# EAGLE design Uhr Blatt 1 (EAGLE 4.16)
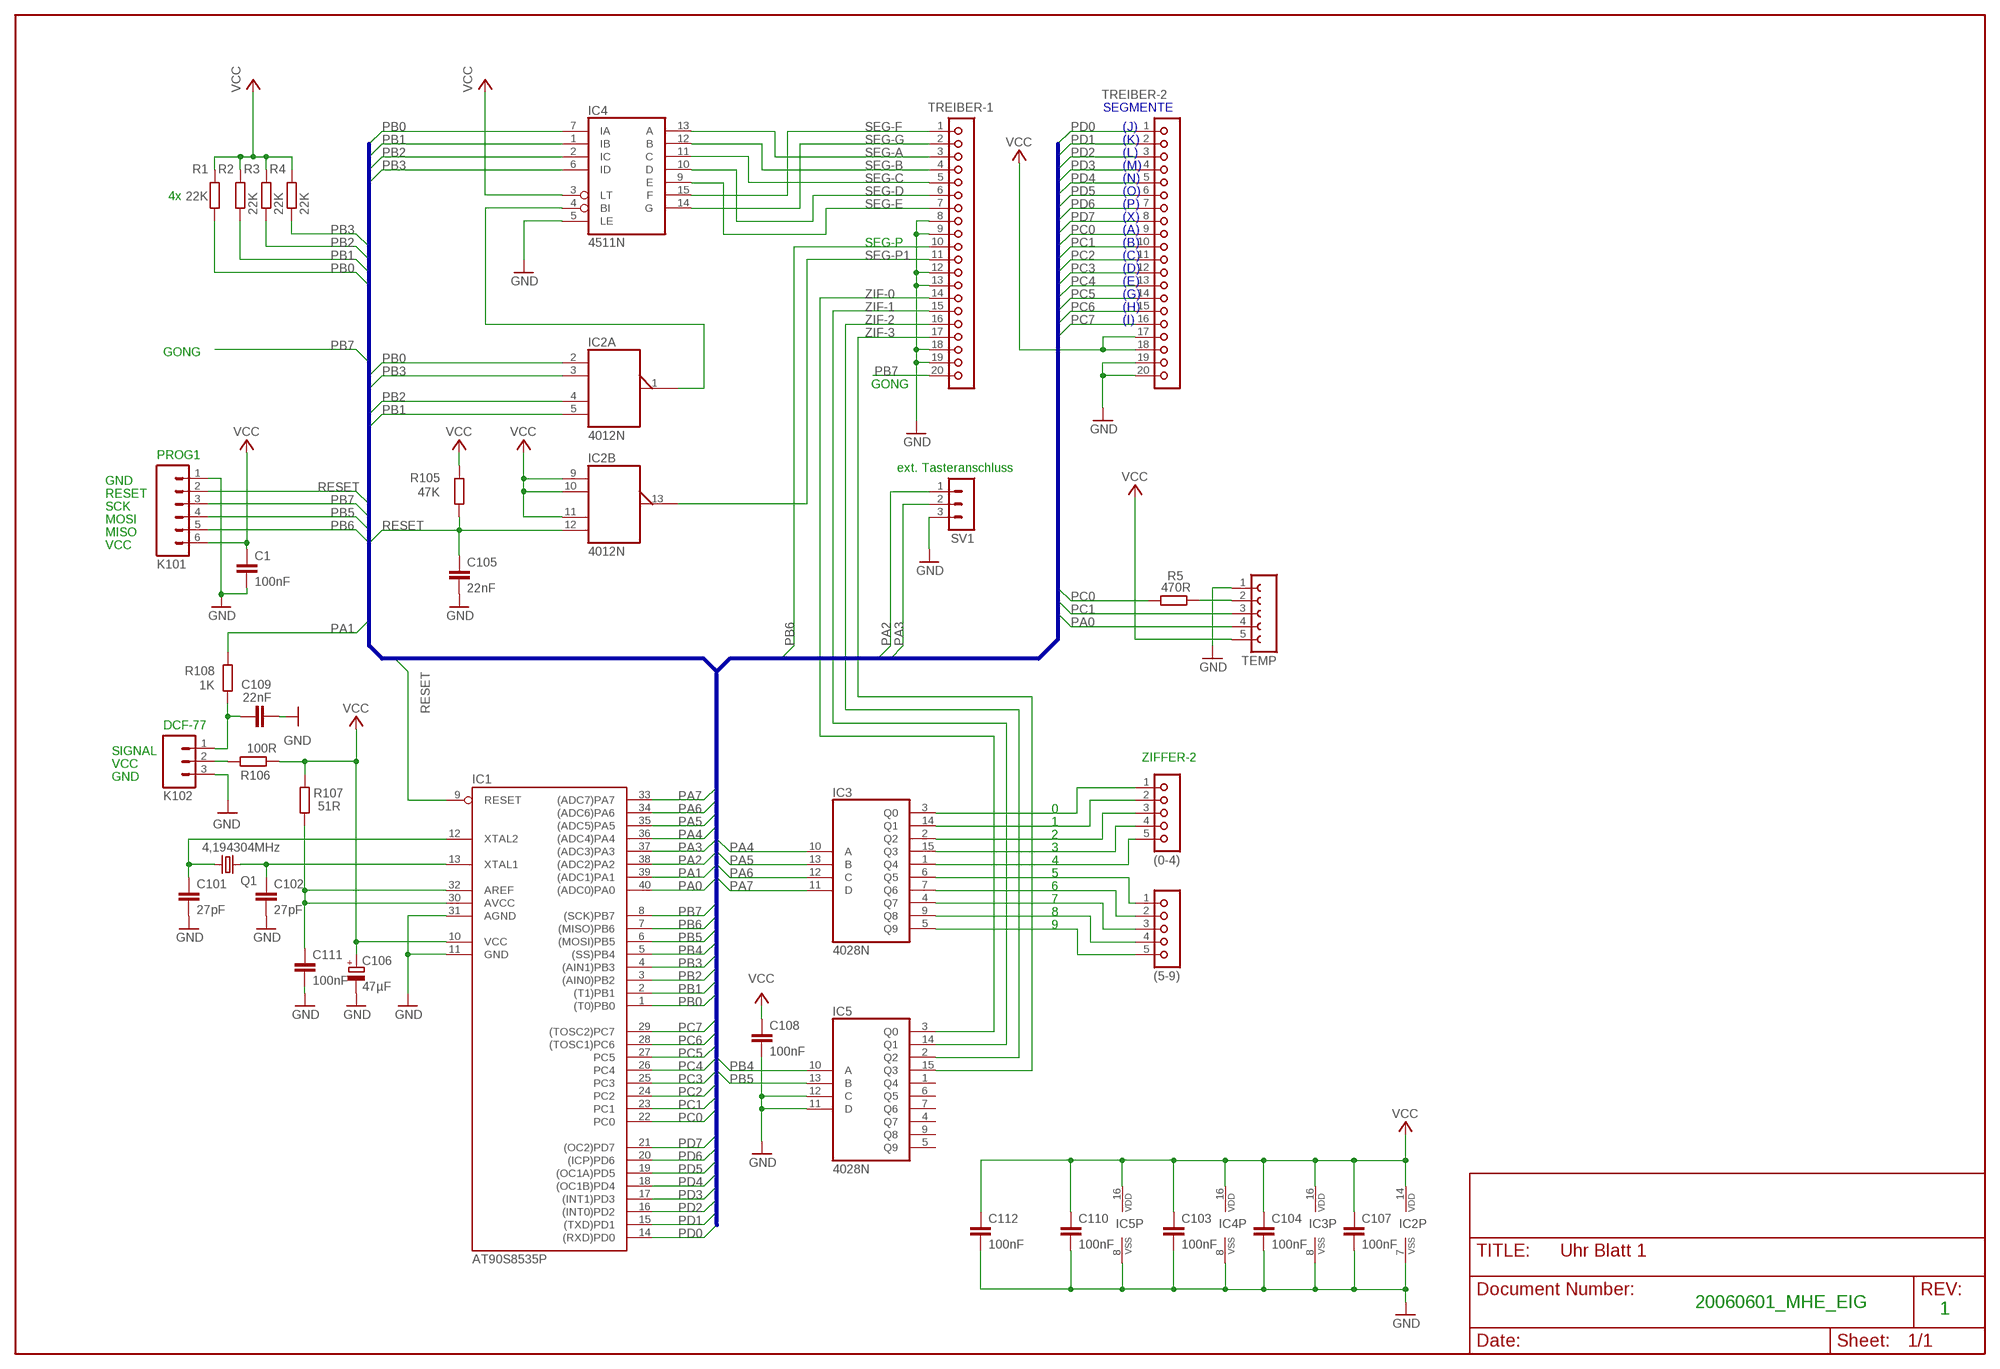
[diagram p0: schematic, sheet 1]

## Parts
(0-4)  JU05  [JU05]
(5-9)  JU05  [JU05]
C1  100nF  C-EU050-024X044  [C050-024X044]
C101  27pF  C-EU025-024X044  [C025-024X044]
C102  27pF  C-EU025-024X044  [C025-024X044]
C103  100nF  C-EU050-024X044  [C050-024X044]
C104  100nF  C-EU050-024X044  [C050-024X044]
C105  22nF  C-EU050-024X044  [C050-024X044]
C106  47µF  CPOL-EUE2,5-6E  [E2,5-6E]
C107  100nF  C-EU050-024X044  [C050-024X044]
C108  100nF  C-EU050-024X044  [C050-024X044]
C109  22nF  C-EU050-024X044  [C050-024X044]
C110  100nF  C-EU050-024X044  [C050-024X044]
C111  100nF  C-EU050-024X044  [C050-024X044]
C112  100nF  C-EU050-024X044  [C050-024X044]
IC1  AT90S8535P  [DIL40]
IC2  4012N  [DIL14]
IC3  4028N  [DIL16]
IC4  4511N  [DIL16]
IC5  4028N  [DIL16]
K101  M06  [06P]
K102  M03  [03P]
Q1  4,194304MHz  CRYTALHC49U-V  [HC49U-V]
R1  22K  R-EU_0207/10  [0207/10]
R2  22K  R-EU_0207/10  [0207/10]
R3  22K  R-EU_0207/10  [0207/10]
R4  22K  R-EU_0207/10  [0207/10]
R5  470R  R-EU_0207/10  [0207/10]
R105  47K  R-EU_0207/10  [0207/10]
R106  100R  R-EU_0207/10  [0207/10]
R107  51R  R-EU_0207/10  [0207/10]
R108  1K  R-EU_0207/10  [0207/10]
SV1  MA03-1  [MA03-1]
TEMP  FE05-1  [FE05-1]
TREIBER-1  JU20  [JU20]
TREIBER-2  JU20  [JU20]

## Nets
AVCC: C111.1 IC1.30(AVCC) IC1.32(AREF) R107.1
DCF77: C109.1 K102.1 R108.1
GND: C1.2 C101.2 C102.2 C103.2 C104.2 C105.2 C106.- C107.2 C108.2 C109.2 C110.2 C111.2 C112.2 IC1.11(GND) IC1.31(AGND) IC2.7(P:VSS) IC3.8(VSS) IC4.5(LE) IC4.8(VSS) IC5.8(VSS) IC5.11(D) IC5.12(C) K101.1 K102.3 SV1.3 TEMP.1 TREIBER-1.8 TREIBER-1.9 TREIBER-1.12 TREIBER-1.13 TREIBER-1.18 TREIBER-1.19 TREIBER-2.19 TREIBER-2.20
N$1: IC2.1 IC4.4(BI)
N$2: C101.1 IC1.12(XTAL2) Q1.1
N$3: C102.1 IC1.13(XTAL1) Q1.2
N$5: K102.2 R106.1
N$6: (0-4).1 IC3.3(Q0)
N$7: (0-4).2 IC3.14(Q1)
N$8: (0-4).3 IC3.2(Q2)
N$9: (0-4).4 IC3.15(Q3)
N$10: (0-4).5 IC3.1(Q4)
N$11: (5-9).1 IC3.6(Q5)
N$12: (5-9).2 IC3.7(Q6)
N$13: (5-9).3 IC3.4(Q7)
N$14: (5-9).4 IC3.9(Q8)
N$15: (5-9).5 IC3.5(Q9)
N$16: R5.2 TEMP.2
PA0: IC1.40((ADC0)PA0) TEMP.4
PA1: IC1.39((ADC1)PA1) R108.2
PA2: IC1.38((ADC2)PA2) SV1.1
PA3: IC1.37((ADC3)PA3) SV1.2
PA4: IC1.36((ADC4)PA4) IC3.10(A)
PA5: IC1.35((ADC5)PA5) IC3.13(B)
PA6: IC1.34((ADC6)PA6) IC3.12(C)
PA7: IC1.33((ADC7)PA7) IC3.11(D)
PB0: IC1.1((T0)PB0) IC2.2(A:I0) IC4.7(IA) R1.1
PB1: IC1.2((T1)PB1) IC2.5(A:I3) IC4.1(IB) R2.1
PB2: IC1.3((AIN0)PB2) IC2.4(A:I2) IC4.2(IC) R3.1
PB3: IC1.4((AIN1)PB3) IC2.3(A:I1) IC4.6(ID) R4.1
PB4: IC1.5((SS)PB4) IC5.10(A)
PB5: IC1.6((MOSI)PB5) IC5.13(B) K101.4
PB6: IC1.7((MISO)PB6) K101.5 TREIBER-1.10
PB7: IC1.8((SCK)PB7) K101.3 TREIBER-1.20
PC0: IC1.22(PC0) R5.1 TREIBER-2.9
PC1: IC1.23(PC1) TEMP.3 TREIBER-2.10
PC2: IC1.24(PC2) TREIBER-2.11
PC3: IC1.25(PC3) TREIBER-2.12
PC4: IC1.26(PC4) TREIBER-2.13
PC5: IC1.27(PC5) TREIBER-2.14
PC6: IC1.28((TOSC1)PC6) TREIBER-2.15
PC7: IC1.29((TOSC2)PC7) TREIBER-2.16
PD0: IC1.14((RXD)PD0) TREIBER-2.1
PD1: IC1.15((TXD)PD1) TREIBER-2.2
PD2: IC1.16((INT0)PD2) TREIBER-2.3
PD3: IC1.17((INT1)PD3) TREIBER-2.4
PD4: IC1.18((OC1B)PD4) TREIBER-2.5
PD5: IC1.19((OC1A)PD5) TREIBER-2.6
PD6: IC1.20((ICP)PD6) TREIBER-2.7
PD7: IC1.21((OC2)PD7) TREIBER-2.8
RESET: C105.1 IC1.9(RESET) IC2.12(B:I3) K101.2 R105.1
SEG-A: IC4.13(A) TREIBER-1.3
SEG-B: IC4.12(B) TREIBER-1.4
SEG-C: IC4.11(C) TREIBER-1.5
SEG-D: IC4.10(D) TREIBER-1.6
SEG-E: IC4.9(E) TREIBER-1.7
SEG-F: IC4.15(F) TREIBER-1.1
SEG-G: IC4.14(G) TREIBER-1.2
SEG-P1: IC2.13 TREIBER-1.11
VCC: C1.1 C103.1 C104.1 C106.+ C107.1 C108.1 C110.1 C112.1 IC1.10(VCC) IC2.9(B:I0) IC2.10(B:I1) IC2.11(B:I2) IC2.14(P:VDD) IC3.16(VDD) IC4.3(LT) IC4.16(VDD) IC5.16(VDD) K101.6 R1.2 R2.2 R3.2 R4.2 R105.2 R106.2 R107.2 TEMP.5 TREIBER-2.17 TREIBER-2.18
ZIF-0: IC5.3(Q0) TREIBER-1.14
ZIF-1: IC5.14(Q1) TREIBER-1.15
ZIF-2: IC5.2(Q2) TREIBER-1.16
ZIF-3: IC5.15(Q3) TREIBER-1.17
Unconnected: IC5.1(Q4) IC5.4(Q7) IC5.5(Q9) IC5.6(Q5) IC5.7(Q6) IC5.9(Q8)

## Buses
B$1

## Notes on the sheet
- SEGMENTE
- (J)
- (K)
- (L)
- (M)
- (N)
- (O)
- 4x
- (P)
- (X)
- (A)
- SEG-P | (B)
- (C)
- (D)
- (E)
- (G)
- (H)
- (I)
- GONG
- GONG
- PROG1
- ext. Tasteranschluss
- GND
- RESET
- SCK
- MOSI
- MISO
- VCC
- DCF-77
- SIGNAL
- ZIFFER-2
- VCC
- GND
- 0
- 1
- 2
- 3
- 4
- 5
- 6
- 7
- 8
- 9
- 20060601_MHE_EIG
- 1

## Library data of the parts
(0-4) (5-9) = con-lsta:JU05: PIN HEADER
C1 C101-C105 C107-C112 = rcl:C-EU: CAPACITOR, European symbol
C106 = rcl:CPOL-EU: POLARIZED CAPACITOR, European symbol
IC1 = atmel:AT90*8535P: MICROCONTROLLER 8 Kbytes FLASH 512 bytes SRAM 512 bytes EEPROM UART 8-channel 10 bit ADC
IC2 = 40xx:4012N
IC3 IC5 = 40xx:4028: BCD to decimal DECODER
IC4 = 45xx:4511: BCD to 7-segment LATCH/DECODER/DRIVER
K101 = con-amp-quick:M06: AMP QUICK CONNECTOR
K102 = con-amp-quick:M03: AMP QUICK CONNECTOR
Q1 = crystal:CRYTAL: CRYSTAL
R1-R5 R105-R108 = rcl:R-EU_: RESISTOR, European symbol
SV1 = con-lstb:MA03-1: PIN HEADER
TEMP = con-lsta:FE05-1: FEMALE HEADER
TREIBER-1 TREIBER-2 = con-lsta:JU20: PIN HEADER

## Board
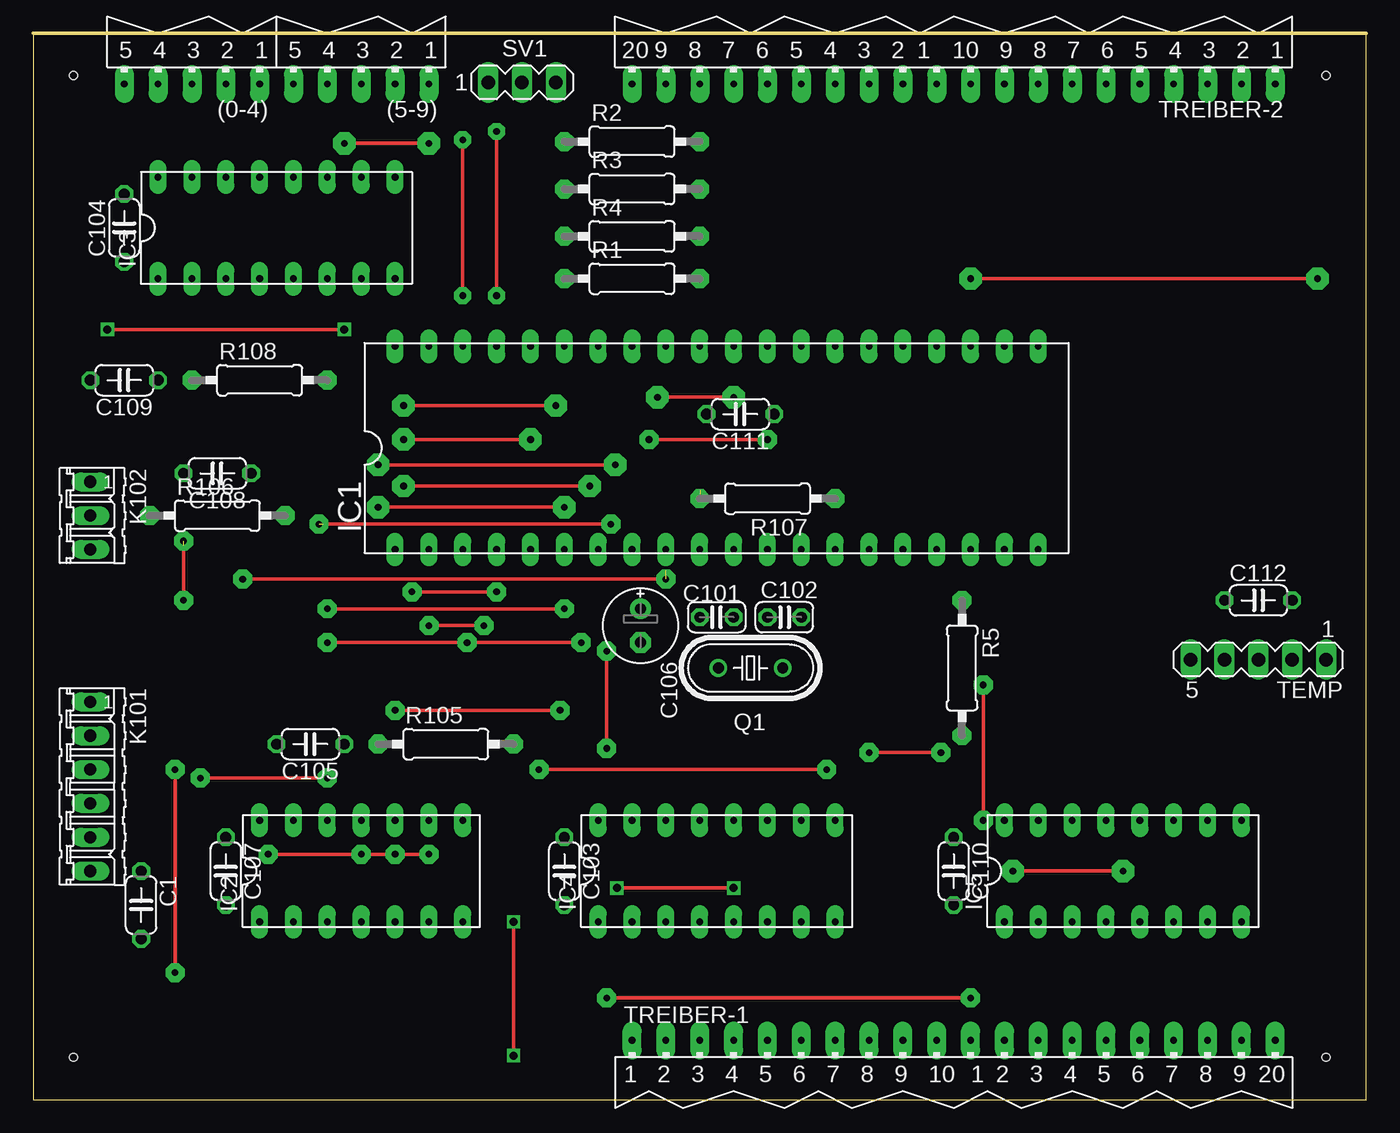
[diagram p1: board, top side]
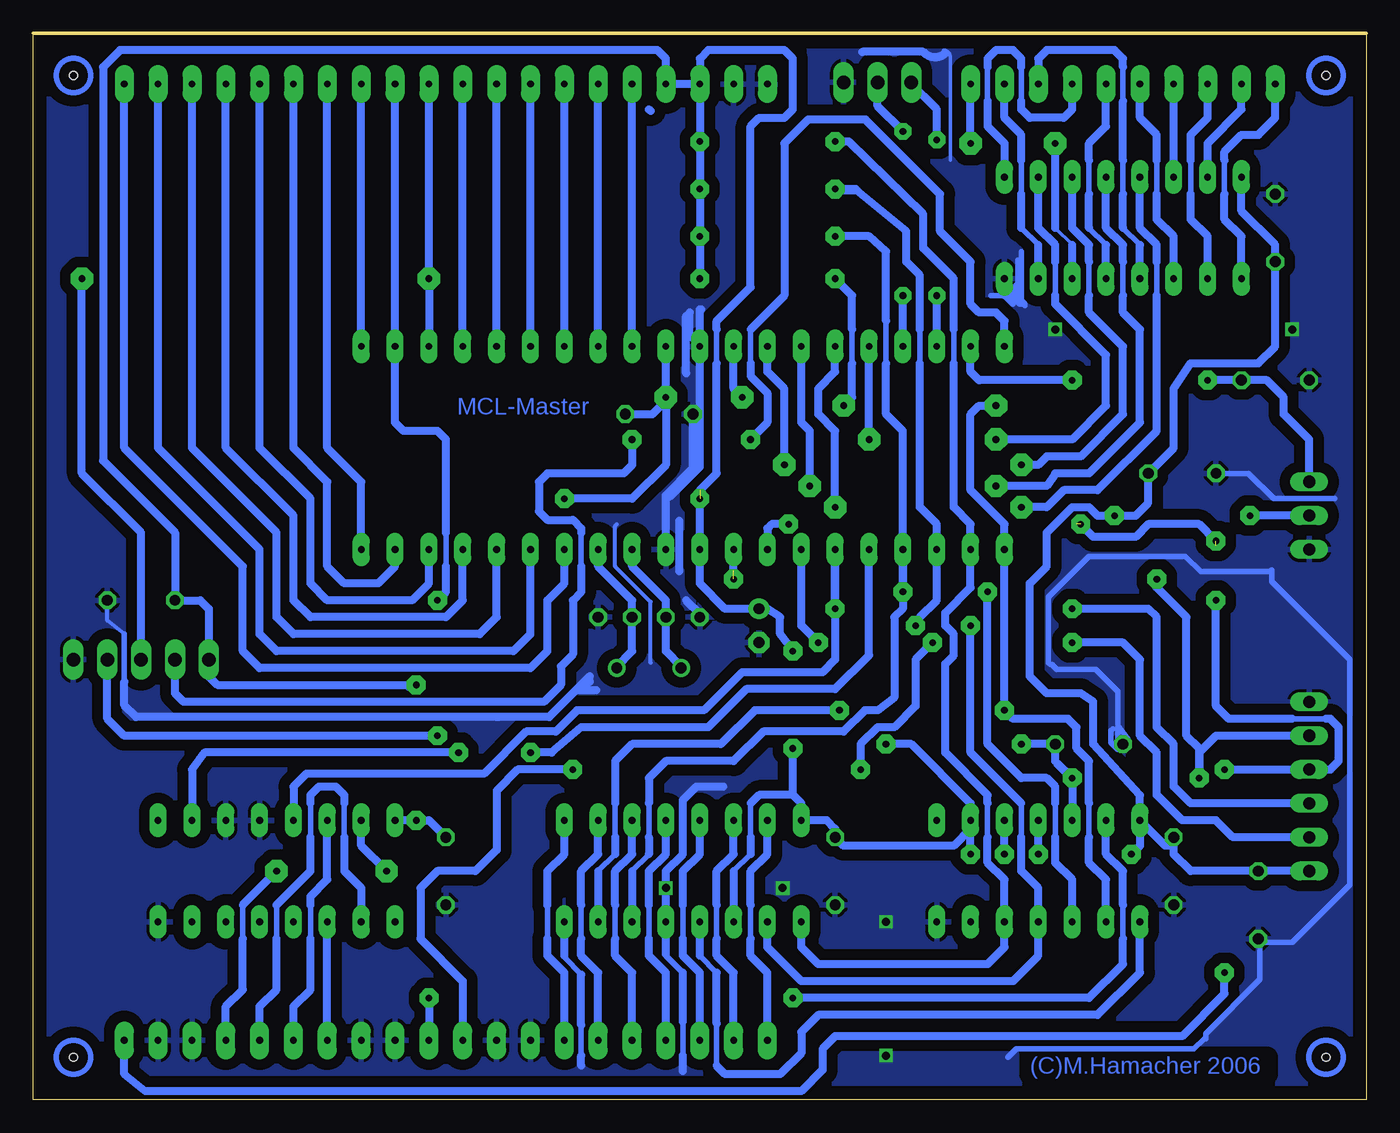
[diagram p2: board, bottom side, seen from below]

Size 100 x 80 mm. Coordinates in mm from the lower left corner, seen from the top.
Outline: 0,0 100,0 100,80 0,80 0,0
Copper layers (1*16): Top 0.035mm / dielectric 1.5mm / Bottom 0.035mm
Design rules "default": minimum track width 10mil, minimum drill 24mil, track to track 8mil, track to pad 8mil, pad to pad 8mil, via to via 8mil, smd to smd 8mil, copper to edge 40mil, drill to drill 8mil, minimum pad ring 10mil, minimum via ring 8mil, stop-mask expansion 4mil, vias tented up to drill 0mil, thermal gap 10mil
Holes 0.6 mm at 3.01,3.17 96.99,76.83 96.99,3.17 3.01,76.83

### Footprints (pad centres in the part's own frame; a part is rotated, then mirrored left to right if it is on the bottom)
JU05 = drill 0.5 pad 1.422 long: 1 -5.08,0; 2 -2.54,0; 3 0,0; 4 2.54,0; 5 5.08,0
C050-024X044 = drill 0.813 octagon: 1 -2.54,0; 2 2.54,0
C025-024X044 = drill 0.813 octagon: 1 -1.27,0; 2 1.27,0
E2,5-6E = drill 0.813 pad 1.575 round: + -1.27,0 | drill 0.813 pad 1.575 octagon: - 1.27,0
DIL40 = drill 0.5 pad 1.27 long: 1 -24.13,-7.62; 2 -21.59,-7.62; 3 -19.05,-7.62; 4 -16.51,-7.62; 5 -13.97,-7.62; 6 -11.43,-7.62; 7 -8.89,-7.62; 8 -6.35,-7.62; 9 -3.81,-7.62; 10 -1.27,-7.62; 11 1.27,-7.62; 12 3.81,-7.62; 13 6.35,-7.62; 14 8.89,-7.62; 15 11.43,-7.62; 16 13.97,-7.62; 17 16.51,-7.62; 18 19.05,-7.62; 19 21.59,-7.62; 20 24.13,-7.62; 21 24.13,7.62; 22 21.59,7.62; 23 19.05,7.62; 24 16.51,7.62; 25 13.97,7.62; 26 11.43,7.62; 27 8.89,7.62; 28 6.35,7.62; 29 3.81,7.62; 30 1.27,7.62; 31 -1.27,7.62; 32 -3.81,7.62; 33 -6.35,7.62; 34 -8.89,7.62; 35 -11.43,7.62; 36 -13.97,7.62; 37 -16.51,7.62; 38 -19.05,7.62; 39 -21.59,7.62; 40 -24.13,7.62
DIL14 = drill 0.5 pad 1.27 long: 1 -7.62,-3.81; 2 -5.08,-3.81; 3 -2.54,-3.81; 4 0,-3.81; 5 2.54,-3.81; 6 5.08,-3.81; 7 7.62,-3.81; 8 7.62,3.81; 9 5.08,3.81; 10 2.54,3.81; 11 0,3.81; 12 -2.54,3.81; 13 -5.08,3.81; 14 -7.62,3.81
DIL16 = drill 0.5 pad 1.27 long: 1 -8.89,-3.81; 2 -6.35,-3.81; 3 -3.81,-3.81; 4 -1.27,-3.81; 5 1.27,-3.81; 6 3.81,-3.81; 7 6.35,-3.81; 8 8.89,-3.81; 9 8.89,3.81; 10 6.35,3.81; 11 3.81,3.81; 12 1.27,3.81; 13 -1.27,3.81; 14 -3.81,3.81; 15 -6.35,3.81; 16 -8.89,3.81
06P = drill 0.914 long: 1 -6.35,0; 2 -3.81,0; 3 -1.27,0; 4 1.27,0; 5 3.81,0; 6 6.35,0
03P = drill 0.914 long: 1 -2.54,0; 2 0,0; 3 2.54,0
HC49U-V = drill 0.813 round: 1 -2.413,0; 2 2.413,0
0207/10 = drill 0.5 pad 1.422 octagon: 1 -5.08,0; 2 5.08,0
MA03-1 = drill 1.016 long: 1 -2.54,0; 2 0,0; 3 2.54,0
MA05-1 = drill 1.016 long: 1 -5.08,0; 2 -2.54,0; 3 0,0; 4 2.54,0; 5 5.08,0
JU20 = drill 0.5 pad 1.422 long: 1 -24.13,0; 2 -21.59,0; 3 -19.05,0; 4 -16.51,0; 5 -13.97,0; 6 -11.43,0; 7 -8.89,0; 8 -6.35,0; 9 -3.81,0; 10 -1.27,0; 11 1.27,0; 12 3.81,0; 13 6.35,0; 14 8.89,0; 15 11.43,0; 16 13.97,0; 17 16.51,0; 18 19.05,0; 19 21.59,0; 20 24.13,0

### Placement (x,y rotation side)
(0-4)  11.9,76.19 180 top
(5-9)  24.6,76.19 180 top
C1  8.09,14.6 270 top
C101  51.27,36.19 180 top
C102  56.35,36.19 0 top
C103  39.84,17.14 270 top
C104  6.82,65.4 90 top
C105  20.79,26.66 180 top
C106  45.55,35.55 270 top
C107  14.44,17.14 270 top
C108  13.81,46.98 180 top
C109  6.82,53.97 180 top
C110  69.05,17.14 270 top
C111  53.05,51.43 180 top
C112  91.91,37.46 0 top
IC1  51.27,48.89 0 top
IC2  24.6,17.14 0 top
IC3  18.25,65.4 0 top
IC4  51.27,17.14 0 top
IC5  81.75,17.14 0 top
K101  4.28,23.49 270 top
K102  4.28,43.81 270 top
Q1  53.81,32.38 0 top
R1  44.92,61.59 0 top
R2  44.92,71.88 0 top
R3  44.92,68.32 0 top
R4  44.92,64.77 0 top
R5  69.69,32.38 270 top
R105  30.95,26.66 0 top
R106  13.81,43.81 0 top
R107  55.08,45.08 180 top
R108  16.98,53.97 0 top
SV1  36.66,76.32 0 top
TEMP  [MA05-1]  91.91,33.02 180 top
TREIBER-1  69.05,4.44 0 top
TREIBER-2  69.05,76.19 180 top

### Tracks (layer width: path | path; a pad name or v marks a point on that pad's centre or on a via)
AVCC  (via drill 0.5 pad 1.68)
  Top 0.254: v46.82,52.7 v52.54,52.7
  Bottom 0.61: R107.1 55.08,45.08 52.54,47.62 v52.54,52.7 | v52.54,52.7 IC1.30 | v52.54,52.7 52.54,52.45 53.56,51.43 C111.1 | IC1.32 47.46,53.34 v46.82,52.7
DCF77
  Bottom 0.61: R108.1 C109.1 7.46,53.97 6.18,52.7 6.18,51.43 4.28,49.53 K102.1
GND  (via drill 0.6)
  Top 0.254: v36.03,13.33 v36.03,3.3 36.03,3.17 | 43.65,15.87 v43.78,15.87 v52.54,15.87 | v5.55,57.78 v23.33,57.78
  Bottom 0.254: 31.2,70.48 31.2,78.23 arc-90 31.71,78.73 31.58,78.48 | 48.22,23.49 48.09,23.62
  Bottom 0.305: 53.68,32.76 53.68,37.33 56.35,40 56.35,43.05 56.22,43.18 | C112.2 94.45,35.94 93.18,34.92
  Bottom 0.406: C105.2 18.63,27.05 18.63,28.06 | 18.63,28.06 18.63,28.95 | 17.87,27.05 18.63,28.06 | 19.01,27.81 19.14,27.68 19.14,26.79 18.63,26.28 18.63,30.6 20.28,32.25 23.2,32.25 23.58,32.63 23.71,32.63 23.84,32.76 23.84,37.71 20.79,40.76 13.55,40.76 12.41,39.62 7.2,39.62 7.07,39.75 7.07,38.86 1.23,33.02 1.23,16.12 5.55,11.81 7.84,11.81 C1.2 8.22,12.06 7.96,11.81 7.96,9.01 12.03,4.95 12.03,4.57 12.15,4.57 12.92,3.8 26.25,3.8 26.89,3.17 | 1.23,24.38 1.23,29.33 | 2.38,45.08 6.95,45.08 8.85,46.98 C108.2 | IC3.8 27.14,60.83 26,59.69 25.87,59.69 25.87,61.46 | 26.5,59.69 27.27,60.45 | 25.62,59.56 25.62,59.69 26.25,60.32 | 26.25,60.32 26.76,60.83 | 28.16,60.32 27.01,60.32 25.87,61.46 | 25.87,61.46 25.87,63.62 | 26.25,60.32 arc-90 26.12,60.45 26.12,62.99 | 52.54,10.92 52.54,10.79 51.27,9.52 | 51.27,3.3 51.27,5.84 | 60.16,10.79 60.16,10.66 58.89,9.39 | 58.89,3.3 58.89,5.58 | 93.18,31.36 93.18,34.92
  Bottom 0.61: 50,36.32 50,36.44 51.02,37.46 | 52.29,45.21 50,47.49 IC1.31 50,59.3 49.87,59.3 | 51.52,39.62 51.52,43.43 | 50,56.64 50.76,57.4 50.76,59.05 | 51.02,54.48 51.02,58.8 50.89,58.8 | 52.54,10.92 IC4.5 v52.54,15.87 52.54,17.14 51.27,18.41 51.27,22.47 50.25,23.49 48.22,23.49 | 51.27,5.84 51.27,9.52 | 51.27,2.15 51.27,3.3 | 60.16,10.79 IC4.8 | 58.89,2.54 58.89,3.3 | 58.89,5.58 58.89,9.39 | 93.18,31.36 93.18,29.59 92.29,28.7 65.24,28.7 | 65.24,28.7 65.11,28.7 | 65.24,28.7 61.3,28.7 59.27,30.73 | 59.27,30.73 57.75,30.73 | 59.27,30.73 58.25,31.74 58.25,31.36 58.76,30.86 | 31.58,78.48 arc90 33.24,78.61 37.81,78.61 | IC1.11 52.54,45.33 50.51,47.37 C111.2 50.63,51.56
  pour Bottom (isolate 0.813): 0.47,0.63 0.47,79.37 99.53,79.37 99.53,0.63
N$1
  Bottom 0.406: 48.73,2.54 48.73,5.71 | 48.73,9.52 50,10.79
  Bottom 0.61: IC2.1 16.98,9.52 20.15,6.34 41.11,6.34 42.38,5.08 42.38,3.49 43.97,1.9 48.09,1.9 48.73,2.54 | 48.73,5.71 48.73,9.52 | 50,10.79 IC4.4
N$2
  Bottom 0.61: Q1.1 51.4,32.51 52.54,33.65 C101.1 52.54,37.46 55.08,40 IC1.12
N$3
  Bottom 0.61: Q1.2 56.22,32.51 55.08,33.65 C102.1 55.08,37.46 57.62,40 IC1.13
N$5
  Bottom 0.61: K102.2 R106.1
N$6
  Bottom 0.406: 15.71,67.94 15.71,70.48
  Bottom 0.61: IC3.3 14.44,64.77 15.71,66.03 15.71,67.94 | 15.71,70.48 15.71,72.38 16.98,73.66 (0-4).1
N$7
  Bottom 0.61: IC3.14 (0-4).2
N$8
  Bottom 0.406: 13.17,67.94 13.17,70.48
  Bottom 0.61: IC3.2 11.9,64.77 13.17,66.03 13.17,67.94 | 13.17,70.48 13.17,72.38 11.9,73.66 (0-4).3
N$9
  Bottom 0.61: IC3.15 11.9,71.75 9.36,74.29 (0-4).4
N$10
  Bottom 0.406: 10.63,67.94 10.63,70.48
  Bottom 0.61: IC3.1 9.36,64.77 10.63,66.03 10.63,67.94 | 10.63,70.48 10.63,71.11 9.36,72.38 8.09,72.38 6.82,73.66 (0-4).5
N$11  (via drill 0.5 pad 1.68)
  Top 0.254: v23.33,71.75 v29.68,71.75
  Bottom 0.254: 22.06,64.13 23.33,65.4
  Bottom 0.61: IC3.6 22.06,64.13 | 23.33,65.4 v23.33,71.75 | v29.68,71.75 (5-9).1
N$12
  Bottom 0.406: 24.6,64.13 25.87,65.4 | 25.87,67.94 25.87,70.48
  Bottom 0.61: IC3.7 24.6,64.13 | 25.87,65.4 25.87,67.94 | 25.87,70.48 25.87,72.38 27.14,73.66 (5-9).2
N$13
  Bottom 0.406: 16.98,64.13 18.25,65.4 | 18.25,67.94 18.25,70.48 | 18.25,74.92 18.25,77.46
  Bottom 0.61: IC3.4 16.98,64.13 | 18.25,65.4 18.25,67.94 | 18.25,70.48 18.25,74.92 | 18.25,77.46 18.25,78.1 18.88,78.73 23.96,78.73 24.6,78.1 (5-9).3
N$14
  Bottom 0.406: 28.41,77.46 28.41,74.92 | 25.87,74.92 25.87,77.46
  Bottom 0.61: IC3.9 27.14,71.75 28.41,73.02 28.41,74.92 | 28.41,77.46 28.41,78.1 27.77,78.73 26.5,78.73 25.87,78.1 25.87,77.46 | 25.87,74.92 25.87,74.29 25.23,73.66 22.7,73.66 22.06,74.29 (5-9).4
N$15
  Bottom 0.406: 19.52,64.13 20.79,65.4 | 20.79,67.94 20.79,70.48
  Bottom 0.61: IC3.5 19.52,64.13 | 20.79,65.4 20.79,67.94 | 20.79,70.48 20.79,71.75 19.52,73.02 (5-9).5
N$16
  Bottom 0.61: R5.2 93.18,27.3 94.45,28.57 TEMP.2
PA0  (via drill 0.5 pad 1.42)
  Top 0.254: v46.19,49.53 v55.08,49.53
  Bottom 0.406: 46.19,57.78 46.19,55.24 | 58.89,42.54 58.89,40
  Bottom 0.61: TEMP.4 89.37,30.47 88.73,29.84 61.68,29.84 60.41,31.11 60.41,32.51 59.52,33.4 59.52,37.46 58.89,38.1 58.89,40 | IC1.40 27.14,58.41 27.77,59.05 29.04,59.05 29.68,59.69 29.68,62.86 31.97,65.15 31.97,67.94 37.55,73.53 41.87,73.53 43.65,71.75 43.65,60.32 46.19,57.78 | 46.19,55.24 46.19,54.29 44.92,53.02 44.92,50.8 v46.19,49.53 | 58.89,42.54 58.89,42.86 59.52,43.49 61.43,43.49 62.06,44.13 62.06,46.35 61.43,46.98 55.71,46.98 55.08,47.62 v55.08,49.53
PA1
  Bottom 0.61: R108.2 29.04,53.97 29.68,54.61 IC1.39
PA2  (via drill 0.5 pad 1.27)
  Top 0.254: v32.22,60.32 v32.22,72
  Bottom 0.61: IC1.38 v32.22,60.32 | SV1.1 34.25,76.32 32.22,74.29 v32.22,72
PA3  (via drill 0.5 pad 1.27)
  Top 0.254: v34.76,60.32 v34.76,72.64
  Bottom 0.61: IC1.37 v34.76,60.32 | v34.76,72.64 36.66,74.54 SV1.2
PA4  (via drill 0.5 pad 1.68)
  Top 0.254: v27.77,49.53 v37.3,49.53
  Bottom 0.406: 23.33,60.32 23.33,62.86
  Bottom 0.61: IC3.10 24.6,65.4 23.33,64.13 23.33,62.86 | 23.33,60.32 23.33,59.69 19.52,55.88 19.52,52.07 22.06,49.53 v27.77,49.53 | v37.3,49.53 IC1.36
PA5  (via drill 0.5 pad 1.68)
  Top 0.254: v25.87,44.45 v39.84,44.45
  Bottom 0.406: 15.71,60.32 15.71,62.86
  Bottom 0.61: IC3.13 16.98,65.4 15.71,64.13 15.71,62.86 | 15.71,60.32 15.71,50.16 20.15,45.72 22.7,45.72 23.96,44.45 v25.87,44.45 | v39.84,44.45 39.84,50.16 41.11,51.43 41.11,53.34 39.84,54.61 IC1.35
PA6  (via drill 0.5 pad 1.68)
  Top 0.254: v27.77,46.03 v41.74,46.03
  Bottom 0.406: 18.25,60.32 18.25,62.86
  Bottom 0.61: IC3.12 19.52,65.4 18.25,64.13 18.25,62.86 | 18.25,60.32 18.25,59.05 16.98,57.78 16.98,50.8 20.79,46.98 23.33,46.98 23.96,46.03 v27.77,46.03 | v41.74,46.03 41.74,50.16 42.38,50.8 IC1.34
PA7  (via drill 0.5 pad 1.68)
  Top 0.254: v25.87,47.62 v43.65,47.62
  Bottom 0.406: 20.79,60.32 20.79,62.86
  Bottom 0.61: IC3.11 22.06,65.4 20.79,64.13 20.79,62.86 | 20.79,60.32 20.79,59.05 18.25,56.51 18.25,51.43 21.42,48.26 23.96,48.26 24.6,47.62 v25.87,47.62 | v43.65,47.62 43.65,53.34 44.92,54.61 IC1.33
PB0  (via drill 0.5 pad 1.42, 0.5 pad 1.68)
  Top 0.254: v27.77,52.07 v39.2,52.07 | v27.14,29.2 v39.52,29.2
  Bottom 0.406: 38.57,55.24 38.57,57.78 | 56.35,18.41 57.62,17.14 | 56.35,22.22 56.35,19.68 | 20.79,19.68 20.79,22.22
  Bottom 0.61: R1.1 38.57,60.32 38.57,57.78 | 57.62,17.14 IC4.7 | 38.57,55.24 38.57,52.7 v39.2,52.07 | 56.35,19.68 56.35,18.41 | 56.35,22.22 56.35,25.39 55.08,26.66 48.41,26.66 45.87,29.2 v39.52,29.2 | v27.77,52.07 29.04,52.07 29.68,51.43 29.68,45.72 27.14,43.18 IC1.1 v27.14,29.2 26.5,28.57 22.38,28.57 21.74,27.93 21.74,26.35 20.79,25.39 20.79,22.22 | 20.79,19.68 20.79,17.77 19.52,16.5 IC2.2
PB1
  Bottom 0.406: 30.95,55.24 30.95,57.78 | 28.41,19.68 28.41,22.22
  Bottom 0.61: 30.95,57.78 30.95,61.59 33.24,63.88 33.24,66.42 38.82,71.88 R2.1 | 30.95,55.24 30.95,44.45 29.68,43.18 IC1.2 29.68,38.41 31.58,36.51 31.58,35.55 30.95,34.92 30.95,33.33 31.58,32.7 31.58,26.03 28.41,22.86 28.41,22.22 | IC4.1 42.38,11.43 41.11,10.16 28.41,10.16 27.14,11.43 IC2.5 27.14,16.5 28.41,17.77 28.41,19.68
PB2  (via drill 0.5 pad 1.42)
  Top 0.254: v29.68,35.55 v33.81,35.55
  Bottom 0.406: 33.49,55.24 33.49,57.78 | 25.87,19.68 25.87,22.22
  Bottom 0.61: 38.19,68.19 39.84,68.19 | 38.19,68.19 34.51,65.15 34.51,62.86 33.49,61.84 33.49,57.78 | 33.49,55.24 33.49,44.45 32.22,43.18 IC1.3 32.22,37.46 33.49,36.19 v33.81,35.55 | v29.68,35.55 29.68,26.03 25.87,22.22 | 25.87,19.68 25.87,17.14 24.6,15.87 IC2.4 24.6,10.79 26.5,8.89 42.38,8.89 44.92,11.43 IC4.2 | R3.1 38.32,68.32 38.19,68.19
PB3  (via drill 0.5 pad 1.42)
  Top 0.254: v28.41,38.1 v34.76,38.1
  Bottom 0.406: 53.81,18.41 55.08,17.14 | 53.81,22.22 53.81,19.68 | 36.03,55.24 36.03,58.41 | 23.33,19.68 23.33,22.22
  Bottom 0.61: 55.08,17.14 IC4.6 | 53.81,19.68 53.81,18.41 | R4.1 37.3,64.77 36.03,63.62 36.03,58.41 | 36.03,55.24 36.03,51.43 34.76,50.16 IC1.4 | IC2.3 22.06,16.5 23.33,17.77 23.33,19.68 | 23.33,22.22 23.33,23.49 23.96,24.12 25.87,24.12 28.41,26.66 v28.41,38.1 | v34.76,38.1 IC1.4 | IC1.4 34.76,36.83 35.39,36.19 35.39,30.16 36.66,29.2 37.62,29.2 39.2,27.62 45.24,27.62 47.46,25.39 52.54,25.39 53.81,24.12 53.81,22.22
PB4  (via drill 0.5 pad 1.42)
  Top 0.254: v62.7,26.03 v68.1,26.03
  Bottom 0.61: IC5.10 88.1,24.76 87.15,26.03 v68.1,26.03 | IC1.5 37.3,33.33 39.84,30.79 46.51,30.79 49.37,27.93 58.89,27.93 61.11,26.03 v62.7,26.03
PB5  (via drill 0.5 pad 1.42)
  Top 0.254: v22.06,36.83 v39.84,36.83
  Bottom 0.61: v39.84,36.83 IC1.6 39.84,33.02 40.79,32.06 46.82,32.06 49.68,29.2 59.21,29.2 60.8,27.62 63.02,27.62 66.19,24.44 79.53,24.44 80.48,23.49 IC5.13 | v22.06,36.83 16.34,36.83 15.71,36.19 15.71,27.93 14.44,26.66 14.44,23.49 13.17,22.22 K101.4
PB6  (via drill 0.5 pad 1.42)
  Top 0.254: v22.06,34.29 v32.54,34.29 v41.11,34.29 | v37.94,24.76 v59.52,24.76
  Bottom 0.61: K101.5 10,19.68 11.27,20.95 13.81,20.95 15.71,22.86 15.71,26.03 16.98,27.3 16.98,33.02 18.25,34.29 v22.06,34.29 | IC1.7 42.38,35.55 v41.11,34.29 | TREIBER-1.10 67.78,8.89 70.95,12.06 70.95,15.87 69.69,17.14 66.83,17.14 65.24,18.73 65.24,23.17 63.65,24.76 v59.52,24.76 | v37.94,24.76 37.94,26.66 36.66,27.93 35.39,27.93 33.81,29.52 33.81,33.02 v32.54,34.29
PB7  (via drill 0.5 pad 1.42)  (2 unrouted)
  Top 0.254: v11.27,37.46 11.27,41.59 | 21.74,43.18 v43.33,43.18 | v10.63,9.52 v10.63,24.76
  Bottom 0.406: 3.01,28.57 5.55,28.57
  Bottom 0.61: IC1.8 44.92,42.86 44.6,43.18 v43.33,43.18 | v11.27,41.91 12.54,43.18 16.34,43.18 17.3,42.22 20.47,42.22 v21.42,43.18 | 3.01,28.57 2.69,28.57 2.06,27.93 2.06,25.39 2.69,24.76 K101.3 v10.63,24.76 | 5.55,28.57 10.31,28.57 11.27,29.52 v11.27,37.46 | v10.63,9.52 10.63,7.93 13.81,4.76 39.84,4.76 40.79,3.8 40.79,2.22 42.38,0.63 91.59,0.63 93.18,1.9 TREIBER-1.20
PC0
  Bottom 0.406: 69.05,40 69.05,42.54
  Bottom 0.61: TREIBER-2.9 IC1.22 72.86,50.8 72.22,50.16 69.69,50.16 69.05,49.53 69.05,42.54 | 69.05,40 69.05,38.1 R5.1
PC1  (via drill 0.5 pad 1.68)
  Top 0.254: v96.36,61.59 v70.32,61.59
  Bottom 0.61: TREIBER-2.10 v70.32,61.59 IC1.23 | v96.36,61.59 96.36,46.98 91.91,42.54 TEMP.3
PC2
  Bottom 0.61: IC1.24 TREIBER-2.11
PC3
  Bottom 0.61: IC1.25 TREIBER-2.12
PC4
  Bottom 0.61: IC1.26 TREIBER-2.13
PC5
  Bottom 0.61: IC1.27 TREIBER-2.14
PC6
  Bottom 0.61: IC1.28 TREIBER-2.15
PC7
  Bottom 0.61: IC1.29 TREIBER-2.16
PD0
  Bottom 0.61: IC1.14 60.16,38.73 61.43,37.46 61.43,33.65 62.7,32.38 83.02,32.38 84.29,33.65 84.29,40 93.18,48.89 TREIBER-2.1
PD1
  Bottom 0.61: IC1.15 62.7,34.92 63.97,33.65 81.75,33.65 83.02,34.92 83.02,41.27 90.64,48.89 TREIBER-2.2
PD2
  Bottom 0.61: IC1.16 65.24,36.19 66.51,34.92 80.48,34.92 81.75,36.19 81.75,42.54 88.1,48.89 TREIBER-2.3
PD3
  Bottom 0.61: IC1.17 67.78,37.46 69.05,36.19 79.21,36.19 80.48,37.46 80.48,43.81 85.56,48.89 TREIBER-2.4
PD4
  Bottom 0.61: IC1.18 70.32,38.73 71.59,37.46 77.94,37.46 79.21,38.73 79.21,45.08 83.02,48.89 TREIBER-2.5
PD5
  Bottom 0.61: IC1.19 72.86,40 74.13,38.73 76.67,38.73 77.94,40 77.94,46.35 80.48,48.89 TREIBER-2.6
PD6
  Bottom 0.61: IC1.20 75.4,46.35 77.94,48.89 TREIBER-2.7
PD7
  Bottom 0.61: IC1.21 TREIBER-2.8
RESET  (via drill 0.5 pad 1.42)  (1 unrouted)
  Top 0.254: v12.54,24.12 v22.06,24.12 | v15.71,39.05 v47.46,39.05
  Bottom 0.254: 23.17,25.24 23.33,25.08 22.38,24.12 v22.06,24.12 | 23.17,25.24
  Bottom 0.61: IC2.12 v22.06,24.12 23.17,25.24 23.33,25.39 C105.1 R105.1 | K101.2 11.27,27.3 12.54,26.03 v12.54,24.12 12.54,26.35 13.49,27.3 13.49,36.19 15.71,38.41 v15.71,39.05 | 47.46,39.68 IC1.9
S$2
  Bottom 0.61: 53.68,74.16 53.81,74.29
SEG-A
  Bottom 0.406: 51.27,12.06 51.27,14.6
  Bottom 0.61: IC4.13 50,18.41 51.27,17.14 51.27,14.6 | 51.27,12.06 51.27,10.79 50,9.52 TREIBER-1.3
SEG-B
  Bottom 0.406: 53.81,12.06 53.81,14.6
  Bottom 0.61: IC4.12 52.54,18.41 53.81,17.14 53.81,14.6 | 53.81,12.06 53.81,10.79 52.54,9.52 TREIBER-1.4
SEG-C
  Bottom 0.406: 56.35,12.06 56.35,14.6
  Bottom 0.61: IC4.11 55.08,18.41 56.35,17.14 56.35,14.6 | 56.35,12.06 56.35,10.79 55.08,9.52 TREIBER-1.5
SEG-D
  Bottom 0.406: 58.89,12.06 58.89,14.6
  Bottom 0.61: IC4.10 57.62,18.41 58.89,17.14 58.89,14.6 | 58.89,12.06 58.89,10.79 57.62,9.52 TREIBER-1.6
SEG-E
  Bottom 0.406: 61.43,12.06 61.43,14.6
  Bottom 0.61: IC4.9 60.16,18.41 61.43,17.14 61.43,14.6 | 61.43,12.06 61.43,10.79 60.16,9.52 TREIBER-1.7
SEG-F
  Bottom 0.406: 46.19,12.06 46.19,14.6
  Bottom 0.61: IC4.15 44.92,18.41 46.19,17.14 46.19,14.6 | 46.19,12.06 46.19,10.79 44.92,9.52 TREIBER-1.1
SEG-G
  Bottom 0.406: 48.73,12.06 48.73,14.6
  Bottom 0.61: IC4.14 47.46,18.41 48.73,17.14 48.73,14.6 | 48.73,12.06 48.73,10.79 47.46,9.52 TREIBER-1.2
SEG-P1  (via drill 0.5 pad 1.42)
  Top 0.254: v43.02,7.62 v70.32,7.62
  Bottom 0.406: 18.25,12.06 18.25,14.6
  Bottom 0.61: IC2.13 19.52,18.41 18.25,17.14 18.25,14.6 | 18.25,12.06 18.25,10.16 20.79,7.62 v43.02,7.62 | v70.32,7.62 TREIBER-1.11
VCC  (via drill 0.5 pad 1.42)  (1 unrouted)
  Top 0.254: v17.61,18.41 v24.6,18.41 v27.14,18.41 v29.68,18.41 | v43.02,26.35 v43.02,33.65 | v71.27,31.11 v71.27,20.95
  Bottom 0.254: 14.44,20 C107.1 14.44,19.04 | 71.91,31.11 71.91,30.79 71.59,31.11 v71.27,31.11
  Bottom 0.406: 48.73,55.24 48.73,57.78 | 46.19,18.41 47.46,17.14 | 46.19,22.22 46.19,19.68
  Bottom 0.61: IC5.16 v71.27,20.95 70.32,20.95 C110.1 | v71.27,31.11 71.91,31.11 86.19,31.11 86.83,31.74 TEMP.5 86.83,36.83 87.47,37.46 C112.1 89.37,42.54 94.77,47.94 94.77,77.46 93.5,78.73 53.17,78.73 52.54,78.1 TREIBER-2.17 TREIBER-2.18 | TREIBER-2.18 R2.2 R3.2 R4.2 R1.2 | TREIBER-2.18 50,78.1 49.37,78.73 43.65,78.73 43.02,78.1 43.02,74.29 43.65,73.66 45.55,73.66 46.19,73.02 46.19,60.96 48.73,58.41 48.73,57.78 | 48.73,55.24 48.73,46.98 50,45.72 IC1.10 50,38.73 48.09,36.83 C106.+ 44.92,36.83 43.97,36.19 43.97,34.92 v43.02,33.65 | IC3.16 9.36,66.67 6.82,64.13 C104.1 6.82,56.51 8.09,55.24 13.17,55.24 14.44,53.34 14.44,48.89 C108.1 16.34,44.76 17.3,43.81 R106.2 20.15,43.81 20.79,44.45 22.06,44.45 23.96,42.54 23.96,40 25.23,38.73 25.23,31.74 23.96,30.47 21.42,30.47 20.47,29.84 20.47,26.66 16.98,22.86 IC2.14 | C1.1 K101.6 C1.1 | C1.1 13.17,17.14 14.44,18.41 14.44,19.04 15.08,19.04 IC2.14 | IC2.9 29.68,20.31 30.95,19.04 39.2,19.04 C103.1 39.84,20.31 40.48,20.95 IC4.16 42.38,22.22 43.02,22.86 | 47.46,17.14 IC4.3 | 46.19,19.68 46.19,18.41 | 46.19,22.22 45.55,22.86 43.02,22.86 | IC2.14 16.98,19.04 v17.61,18.41 | v24.6,18.41 IC2.11 | v27.14,18.41 IC2.10 | v29.68,18.41 IC2.9 | R105.2 34.12,26.66 29.68,22.22 IC2.9 | 43.02,22.86 v43.02,26.35
ZIF-0
  Bottom 0.61: TREIBER-1.14 IC5.3
ZIF-1
  Bottom 0.406: 79.21,12.06 79.21,14.6
  Bottom 0.61: TREIBER-1.15 80.48,6.98 79.21,8.25 79.21,12.06 | 79.21,14.6 79.21,15.24 77.94,16.5 IC5.14
ZIF-2
  Bottom 0.406: 81.75,12.06 81.75,14.6 | 79.21,19.68 79.21,22.22 | 76.67,22.22 76.67,19.68
  Bottom 0.61: TREIBER-1.16 83.02,6.98 81.75,8.25 81.75,12.06 | 81.75,14.6 79.21,17.14 79.21,19.68 | 79.21,22.22 79.21,22.86 78.58,23.49 77.3,23.49 76.67,22.86 76.67,22.22 | 76.67,19.68 76.67,17.14 75.4,15.87 IC5.2
ZIF-3  (via drill 0.5 pad 1.68)
  Top 0.254: v81.75,17.14 v73.5,17.14
  Bottom 0.406: 84.29,12.06 84.29,14.6
  Bottom 0.61: TREIBER-1.17 85.56,6.98 84.29,8.25 84.29,12.06 | 84.29,14.6 v81.75,17.14 | v73.5,17.14 75.4,19.04 IC5.15
(copper drawn outside any net)
  shapes: Bottom circle x4

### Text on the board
Bottom: MCL-Master | (C)M.Hamacher 2006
